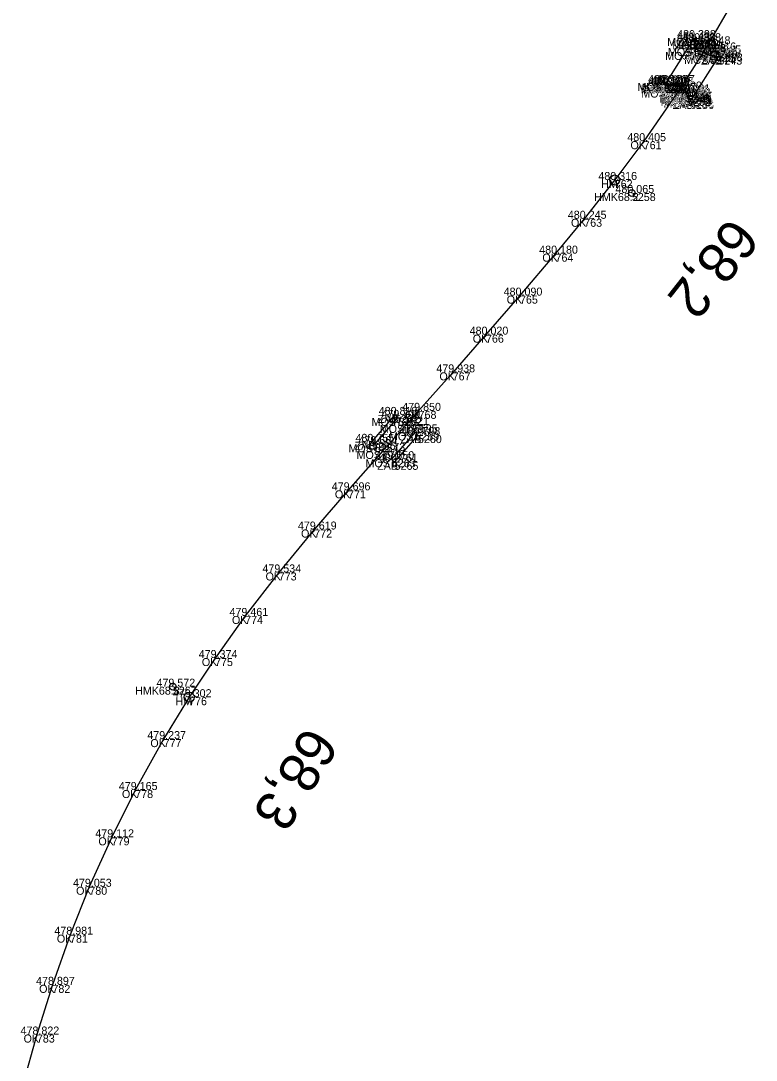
# Model space of a CAD drawing. Extents: x -621782 to -610392, y -1141853 to -1122321.
# Drawn here: x -621487.5 to -621377.2, y -1125189.6 to -1125033.8 of the extents above; entities that cross this region are included whole.
import ezdxf

# ---------------------------------------------------------------- set-up
doc = ezdxf.new("R2010")
doc.units = 0
for name, color, linetype in [('Vrstva 1', 7, 'Continuous'), ('Vrstva 17', 7, 'Continuous'), ('Vrstva 18', 7, 'Continuous'), ('Vrstva 60', 7, 'Continuous'), ('Vrstva 61', 7, 'Continuous'), ('Vrstva 62', 7, 'Continuous'), ('Vrstva 7', 7, 'Continuous')]:
    doc.layers.add(name, color=color, linetype=linetype)

msp = doc.modelspace()

# ---------------------------------------------------------------- linework, layer by layer
at = {"layer": 'Vrstva 1'}
msp.add_lwpolyline([(-621380.85, -1125031.18), (-621384.41, -1125037.3), (-621385.11, -1125038.45), (-621388.7, -1125044.08), (-621394.07, -1125051.82), (-621398.42, -1125057.64), (-621402.99, -1125063.45), (-621407.29, -1125068.68), (-621412.62, -1125074.97), (-621417.72, -1125080.82), (-621422.71, -1125086.47), (-621427.82, -1125092.24), (-621429.69, -1125094.34), (-621433.18, -1125098.25), (-621438.39, -1125104.15), (-621443.46, -1125110.03), (-621448.78, -1125116.46), (-621453.82, -1125122.98), (-621458.33, -1125129.29), (-621462.22, -1125135.16), (-621466.04, -1125141.44), (-621470.3, -1125149.07), (-621473.83, -1125156.16), (-621477.18, -1125163.57), (-621480.07, -1125170.75), (-621482.71, -1125178.27), (-621485.04, -1125185.72), (-621487.19, -1125193.41)], dxfattribs=at)
at = {"layer": 'Vrstva 17'}
for p, q in [((-621390.92, -1125043.41), (-621386.71, -1125036.71)), ((-621382.88, -1125039.15), (-621387.12, -1125045.8)), ((-621434.83, -1125096.89), (-621431.35, -1125092.85)), ((-621427.92, -1125095.87), (-621431.42, -1125099.88))]:
    msp.add_line(p, q, dxfattribs=at)
at = {"layer": 'Vrstva 18'}
for p, q in [((-621434.38, -1125097.24), (-621430.93, -1125093.29)), ((-621431.83, -1125099.49), (-621428.32, -1125095.48))]:
    msp.add_line(p, q, dxfattribs=at)
for points in [[(-621386.61, -1125036.37), (-621385.83, -1125036.84), (-621386.5, -1125037.86), (-621384.07, -1125039.04), (-621383.57, -1125038.22), (-621382.81, -1125038.67)], [(-621387.18, -1125045.61), (-621387.58, -1125045.33), (-621387.43, -1125045.07), (-621387.75, -1125044.83), (-621387.54, -1125044.5), (-621389.77, -1125043.1), (-621389.99, -1125043.43), (-621390.44, -1125043.18), (-621390.59, -1125043.44), (-621391.05, -1125043.11)]]:
    msp.add_lwpolyline(points, dxfattribs=at)
at = {"layer": 'Vrstva 60'}
for p, q in [((-621386.61, -1125036.37), (-621386.61, -1125036.37)), ((-621386.71, -1125036.71), (-621386.71, -1125036.71)), ((-621386.5, -1125037.86), (-621386.5, -1125037.86)), ((-621385.83, -1125036.84), (-621385.83, -1125036.84)), ((-621384.41, -1125037.3), (-621384.41, -1125037.3)), ((-621385.11, -1125038.45), (-621385.11, -1125038.45)), ((-621384.07, -1125039.04), (-621384.07, -1125039.04)), ((-621383.57, -1125038.22), (-621383.57, -1125038.22)), ((-621382.88, -1125039.15), (-621382.88, -1125039.15)), ((-621382.81, -1125038.67), (-621382.81, -1125038.67)), ((-621391.05, -1125043.11), (-621391.05, -1125043.11)), ((-621390.92, -1125043.41), (-621390.92, -1125043.41)), ((-621390.59, -1125043.44), (-621390.59, -1125043.44)), ((-621390.44, -1125043.18), (-621390.44, -1125043.18)), ((-621389.99, -1125043.43), (-621389.99, -1125043.43)), ((-621389.77, -1125043.1), (-621389.77, -1125043.1)), ((-621388.7, -1125044.08), (-621388.7, -1125044.08)), ((-621387.75, -1125044.83), (-621387.75, -1125044.83)), ((-621387.58, -1125045.33), (-621387.58, -1125045.33)), ((-621387.54, -1125044.5), (-621387.54, -1125044.5)), ((-621387.43, -1125045.07), (-621387.43, -1125045.07)), ((-621387.18, -1125045.61), (-621387.18, -1125045.61)), ((-621387.12, -1125045.8), (-621387.12, -1125045.8)), ((-621394.07, -1125051.82), (-621394.07, -1125051.82)), ((-621398.42, -1125057.64), (-621398.42, -1125057.64)), ((-621395.85, -1125059.59), (-621395.85, -1125059.59)), ((-621402.99, -1125063.45), (-621402.99, -1125063.45)), ((-621407.29, -1125068.68), (-621407.29, -1125068.68)), ((-621412.62, -1125074.97), (-621412.62, -1125074.97)), ((-621417.72, -1125080.82), (-621417.72, -1125080.82)), ((-621422.71, -1125086.47), (-621422.71, -1125086.47)), ((-621427.82, -1125092.24), (-621427.82, -1125092.24)), ((-621431.35, -1125092.85), (-621431.35, -1125092.85)), ((-621430.93, -1125093.29), (-621430.93, -1125093.29)), ((-621429.69, -1125094.34), (-621429.69, -1125094.34)), ((-621428.32, -1125095.48), (-621428.32, -1125095.48)), ((-621434.83, -1125096.89), (-621434.83, -1125096.89)), ((-621434.38, -1125097.24), (-621434.38, -1125097.24)), ((-621427.92, -1125095.87), (-621427.92, -1125095.87)), ((-621433.18, -1125098.25), (-621433.18, -1125098.25)), ((-621431.83, -1125099.49), (-621431.83, -1125099.49)), ((-621431.42, -1125099.88), (-621431.42, -1125099.88)), ((-621438.39, -1125104.15), (-621438.39, -1125104.15)), ((-621443.46, -1125110.03), (-621443.46, -1125110.03)), ((-621448.78, -1125116.46), (-621448.78, -1125116.46)), ((-621453.82, -1125122.98), (-621453.82, -1125122.98)), ((-621458.33, -1125129.29), (-621458.33, -1125129.29)), ((-621464.66, -1125133.58), (-621464.66, -1125133.58)), ((-621462.22, -1125135.16), (-621462.22, -1125135.16)), ((-621466.04, -1125141.44), (-621466.04, -1125141.44)), ((-621470.3, -1125149.07), (-621470.3, -1125149.07)), ((-621473.83, -1125156.16), (-621473.83, -1125156.16)), ((-621477.18, -1125163.57), (-621477.18, -1125163.57)), ((-621480.07, -1125170.75), (-621480.07, -1125170.75)), ((-621482.71, -1125178.27), (-621482.71, -1125178.27)), ((-621485.04, -1125185.72), (-621485.04, -1125185.72))]:
    msp.add_line(p, q, dxfattribs=at)
at = {"layer": 'Vrstva 7'}
for p, q in [((-621395.82, -1125059.55), (-621395.89, -1125059.63)), ((-621464.63, -1125133.54), (-621464.69, -1125133.62))]:
    msp.add_line(p, q, dxfattribs=at)
for centre, radius in [((-621398.42, -1125057.64), 0.75), ((-621395.85, -1125059.59), 0.5), ((-621464.66, -1125133.58), 0.5), ((-621462.22, -1125135.16), 0.75)]:
    msp.add_circle(centre, radius, dxfattribs=at)

# ---------------------------------------------------------------- texts
at = {"layer": 'Vrstva 60'}
for s, p in [('5241', (-621386.61, -1125037.57)), ('5242', (-621386.71, -1125037.91)), ('5245', (-621386.5, -1125039.06)), ('5239', (-621385.83, -1125038.04)), ('758', (-621384.41, -1125038.51)), ('759', (-621385.11, -1125039.65)), ('5244', (-621384.07, -1125040.24)), ('5240', (-621383.57, -1125039.42)), ('5243', (-621382.88, -1125040.35)), ('5238', (-621382.81, -1125039.87)), ('5254', (-621391.05, -1125044.31)), ('5257', (-621390.92, -1125044.6)), ('5255', (-621390.59, -1125044.64)), ('5251', (-621390.44, -1125044.38)), ('5250', (-621389.99, -1125044.63)), ('5247', (-621389.77, -1125044.3)), ('760', (-621388.7, -1125045.28)), ('5248', (-621387.75, -1125046.03)), ('5252', (-621387.58, -1125046.53)), ('5246', (-621387.54, -1125045.7)), ('5249', (-621387.43, -1125046.27)), ('5253', (-621387.18, -1125046.81)), ('5256', (-621387.12, -1125047)), ('761', (-621394.07, -1125053.02)), ('762', (-621398.42, -1125058.84)), ('5258', (-621395.85, -1125060.79)), ('763', (-621402.99, -1125064.65)), ('764', (-621407.29, -1125069.88)), ('765', (-621412.62, -1125076.17)), ('766', (-621417.72, -1125082.02)), ('767', (-621422.71, -1125087.67)), ('768', (-621427.82, -1125093.44)), ('5261', (-621431.35, -1125094.05)), ('5262', (-621430.93, -1125094.49)), ('769', (-621429.69, -1125095.54)), ('5259', (-621428.32, -1125096.68)), ('5266', (-621434.83, -1125098.08)), ('5264', (-621434.38, -1125098.44)), ('5260', (-621427.92, -1125097.07)), ('770', (-621433.18, -1125099.45)), ('5263', (-621431.83, -1125100.69)), ('5265', (-621431.42, -1125101.08)), ('771', (-621438.39, -1125105.35)), ('772', (-621443.46, -1125111.23)), ('773', (-621448.78, -1125117.66)), ('774', (-621453.82, -1125124.18)), ('775', (-621458.33, -1125130.49)), ('5267', (-621464.66, -1125134.78)), ('776', (-621462.22, -1125136.36)), ('777', (-621466.04, -1125142.64)), ('778', (-621470.3, -1125150.27)), ('779', (-621473.83, -1125157.36)), ('780', (-621477.18, -1125164.77)), ('781', (-621480.07, -1125171.95)), ('782', (-621482.71, -1125179.47)), ('783', (-621485.04, -1125186.92))]:
    msp.add_text(s, height=1.2, dxfattribs=at).set_placement(p)
at = {"layer": 'Vrstva 61'}
for s, p in [('481.491', (-621389.07, -1125036.71)), ('480.398', (-621389.06, -1125036.37)), ('480.388', (-621388.29, -1125036.84)), ('480.648', (-621386.87, -1125037.3)), ('480.409', (-621388.95, -1125037.86)), ('480.626', (-621387.57, -1125038.45)), ('480.509', (-621386.52, -1125039.04)), ('480.516', (-621386.02, -1125038.22)), ('481.588', (-621385.33, -1125039.15)), ('480.505', (-621385.27, -1125038.67)), ('480.311', (-621393.41, -1125043.11)), ('481.380', (-621393.37, -1125043.41)), ('480.309', (-621393.04, -1125043.44)), ('480.310', (-621392.89, -1125043.18)), ('480.306', (-621392.44, -1125043.43)), ('480.297', (-621392.22, -1125043.1)), ('480.529', (-621391.15, -1125044.08)), ('480.405', (-621390.21, -1125044.83)), ('480.423', (-621390.03, -1125045.33)), ('480.421', (-621389.9, -1125044.5)), ('480.433', (-621389.88, -1125045.07)), ('480.427', (-621389.63, -1125045.61)), ('481.501', (-621389.48, -1125045.8)), ('480.405', (-621396.53, -1125051.82)), ('480.316', (-621400.87, -1125057.64)), ('480.065', (-621398.31, -1125059.59)), ('480.245', (-621405.45, -1125063.45)), ('480.180', (-621409.74, -1125068.68)), ('480.090', (-621415.07, -1125074.97)), ('480.020', (-621420.17, -1125080.82)), ('479.938', (-621425.16, -1125086.47)), ('479.850', (-621430.27, -1125092.24)), ('480.818', (-621433.8, -1125092.85)), ('479.709', (-621433.38, -1125093.29)), ('479.821', (-621432.05, -1125094.34)), ('480.755', (-621437.28, -1125096.89)), ('479.695', (-621430.77, -1125095.48)), ('480.798', (-621430.37, -1125095.87)), ('479.664', (-621436.83, -1125097.24)), ('479.773', (-621435.63, -1125098.25)), ('479.650', (-621434.28, -1125099.49)), ('480.761', (-621433.77, -1125099.88)), ('479.696', (-621440.84, -1125104.15)), ('479.619', (-621445.91, -1125110.03)), ('479.534', (-621451.23, -1125116.46)), ('479.461', (-621456.17, -1125122.98)), ('479.374', (-621460.78, -1125129.29)), ('479.572', (-621467.11, -1125133.58)), ('479.302', (-621464.66, -1125135.16)), ('479.237', (-621468.49, -1125141.44)), ('479.165', (-621472.76, -1125149.07)), ('479.112', (-621476.28, -1125156.16)), ('479.053', (-621479.63, -1125163.57)), ('478.981', (-621482.42, -1125170.75)), ('478.897', (-621485.16, -1125178.27)), ('478.822', (-621487.49, -1125185.72))]:
    msp.add_text(s, height=1.2, dxfattribs=at).set_placement(p)
at = {"layer": 'Vrstva 62'}
for s, p in [('MOST', (-621390.55, -1125037.57)), ('MOST', (-621390.44, -1125039.06)), ('MOST', (-621389.78, -1125038.04)), ('ZAB', (-621389.31, -1125037.91)), ('OK', (-621386.4, -1125038.51)), ('MOSTBS', (-621390.85, -1125039.65)), ('MOST', (-621388.01, -1125040.24)), ('MOST', (-621387.51, -1125039.42)), ('MOST', (-621386.76, -1125039.87)), ('ZAB', (-621385.48, -1125040.35)), ('MOST', (-621394.99, -1125044.31)), ('MOST', (-621394.53, -1125044.64)), ('MOSTBS', (-621394.43, -1125045.28)), ('MOST', (-621394.38, -1125044.38)), ('MOST', (-621393.93, -1125044.63)), ('MOST', (-621393.72, -1125044.3)), ('ZAB', (-621393.52, -1125044.6)), ('MOST', (-621391.7, -1125046.03)), ('MOST', (-621391.53, -1125046.53)), ('MOST', (-621391.48, -1125045.7)), ('MOST', (-621391.37, -1125046.27)), ('MOST', (-621391.12, -1125046.81)), ('ZAB', (-621389.72, -1125047)), ('OK', (-621396.06, -1125053.02)), ('HM', (-621400.45, -1125058.84)), ('HMK68.2', (-621401.51, -1125060.79)), ('OK', (-621404.98, -1125064.65)), ('OK', (-621409.27, -1125069.88)), ('OK', (-621414.61, -1125076.17)), ('OK', (-621419.7, -1125082.02)), ('OK', (-621424.7, -1125087.67)), ('OK', (-621429.81, -1125093.44)), ('MOST', (-621434.87, -1125094.49)), ('ZAB', (-621433.95, -1125094.05)), ('MOST', (-621433.64, -1125095.54)), ('MOST', (-621432.26, -1125096.68)), ('MOST', (-621438.33, -1125098.44)), ('ZAB', (-621437.43, -1125098.08)), ('ZAB', (-621430.52, -1125097.07)), ('MOST', (-621437.12, -1125099.45)), ('MOST', (-621435.78, -1125100.69)), ('ZAB', (-621434.02, -1125101.08)), ('OK', (-621440.37, -1125105.35)), ('OK', (-621445.44, -1125111.23)), ('OK', (-621450.76, -1125117.66)), ('OK', (-621455.8, -1125124.18)), ('OK', (-621460.31, -1125130.49)), ('HMK68.3', (-621470.32, -1125134.78)), ('HM', (-621464.25, -1125136.36)), ('OK', (-621468.03, -1125142.64)), ('OK', (-621472.29, -1125150.27)), ('OK', (-621475.82, -1125157.36)), ('OK', (-621479.16, -1125164.77)), ('OK', (-621482.05, -1125171.95)), ('OK', (-621484.7, -1125179.47)), ('OK', (-621487.03, -1125186.92))]:
    msp.add_text(s, height=1.2, dxfattribs=at).set_placement(p)
at = {"layer": 'Vrstva 7'}
for s, rotation, p in [('68,2', 231.7553, (-621381.1, -1125062.96)), ('68,3', 238.638, (-621444.71, -1125139.25))]:
    msp.add_text(s, height=6, rotation=rotation, dxfattribs=at).set_placement(p)

doc.saveas('drawing.dxf')
